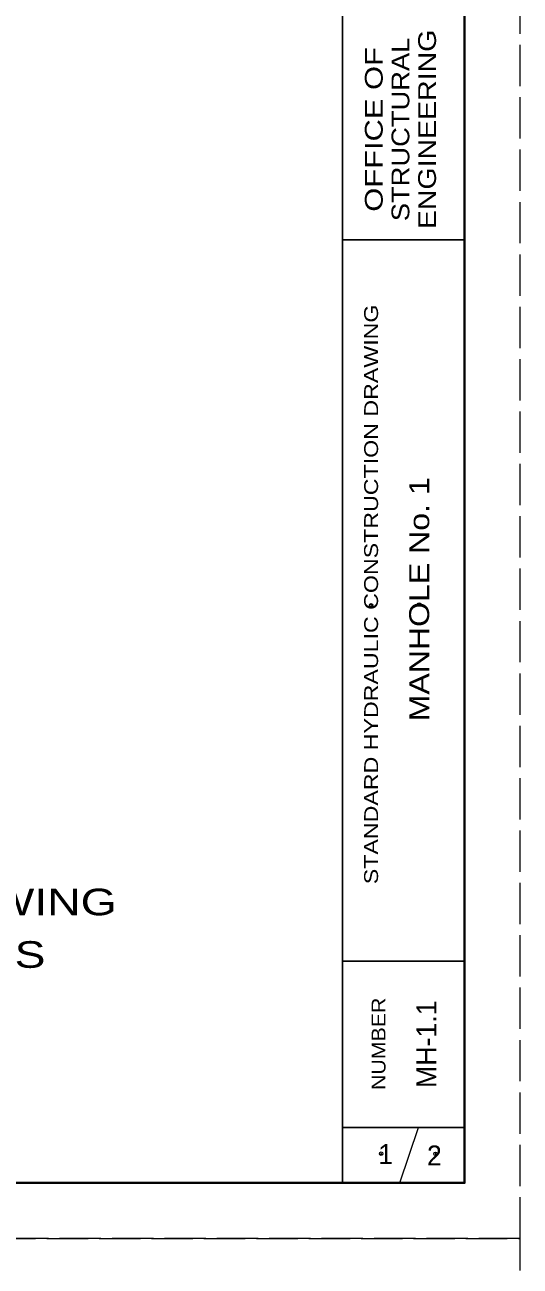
# Model space of a CAD drawing. Extents: x 1083.1 to 1117.1, y 697.4 to 741.4.
# Drawn here: x 1112.66 to 1117.13, y 719.1 to 730.29 of the extents above; entities that cross this region are included whole.
import ezdxf
from ezdxf.enums import TextEntityAlignment as Align

# ---------------------------------------------------------------- set-up
doc = ezdxf.new("R2010")
doc.units = 0
doc.header["$LTSCALE"] = 0.062
doc.header["$PDMODE"] = 32
doc.header["$PDSIZE"] = 0.031
doc.linetypes.add('LONG_DASHED', pattern=[7.5, 6, -1.5])
doc.layers.add('1', color=7, linetype='Continuous', lineweight=13)

msp = doc.modelspace()

# ---------------------------------------------------------------- linework, layer by layer
at = {"layer": '1', "lineweight": 25}
for p, q in [((1115.52642, 719.85408), (1115.52642, 740.85408)), ((1116.62642, 740.85408), (1116.62642, 719.85408)), ((1116.62642, 728.35408), (1115.52642, 728.35408)), ((1116.62642, 721.85408), (1115.52642, 721.85408)), ((1116.62642, 720.35408), (1115.52642, 720.35408))]:
    msp.add_line(p, q, dxfattribs=at)
at = {"layer": '1'}
msp.add_line((1116.04308, 719.85408), (1116.20975, 720.35408), dxfattribs=at)
at = {"layer": '1', "linetype": 'LONG_DASHED'}
for points in [[(1083.12642, 719.35408), (1117.12642, 719.35408), (1117.12642, 741.35408), (1083.12642, 741.35408)], [(1083.12642, 697.35408), (1117.12642, 697.35408), (1117.12642, 719.35408), (1083.12642, 719.35408)]]:
    msp.add_lwpolyline(points, close=True, dxfattribs=at)
at = {"layer": '1', "lineweight": 25}
msp.add_lwpolyline([(1116.62642, 719.85408), (1085.12642, 719.85408), (1085.12642, 740.85408)], dxfattribs=at)
at = {"layer": '1', "lineweight": 40}
msp.add_lwpolyline([(1085.12642, 740.85408), (1116.62642, 740.85408), (1116.62642, 719.85408), (1085.12642, 719.85408)], close=True, dxfattribs=at)
at = {"layer": '1'}
for p in [(1115.78383, 725.06008), (1116.21667, 725.06742), (1115.8745, 720.11783), (1116.36292, 720.11683)]:
    msp.add_point(p, dxfattribs=at)

# ---------------------------------------------------------------- texts
for s, height, width, p in [('ENGINEERING', 0.16, 1.2, (1116.36817, 729.34862)), ('OFFICE OF', 0.16, 1.3, (1115.88817, 729.34854)), ('STRUCTURAL', 0.16, 1.15, (1116.12817, 729.34854)), ('STANDARD HYDRAULIC CONSTRUCTION DRAWING', 0.125, 1.25, (1115.84633, 725.15812)), ('MANHOLE No. 1', 0.18, 1.2, (1116.30683, 725.11421)), ('NUMBER', 0.125, 1.15, (1115.91342, 721.10817))]:
    msp.add_text(s, height=height, rotation=90, dxfattribs=dict(at, width=width)).set_placement(p, align=Align.CENTER)
at = {"layer": '1', "width": 1.3}
for s, p in [('SECTION BELOW SPRING LINE SHOWING', (1105.10017, 722.26617)), ('METHOD OF TURNING SIDE DRAINS', (1105.54942, 721.79283))]:
    msp.add_text(s, height=0.24, dxfattribs=at).set_placement(p)
at = {"layer": '1'}
msp.add_text('MH-1.1', height=0.18, rotation=90, dxfattribs=at).set_placement((1116.3725, 721.10442), align=Align.CENTER)
for s, p in [('1', (1115.91427, 720.02417)), ('2', (1116.35371, 720.01158))]:
    msp.add_text(s, height=0.18, dxfattribs=at).set_placement(p, align=Align.CENTER)

doc.saveas('drawing.dxf')
